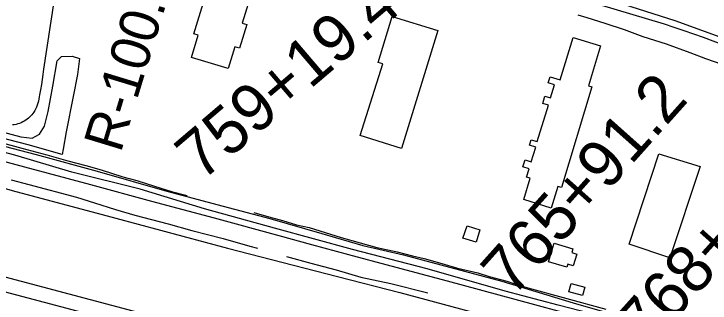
# Model space of a CAD drawing. Extents: x 3651524 to 3689615, y 505651 to 531377.
# Drawn here: x 3663457 to 3664931, y 512320 to 512932 of the extents above; entities that cross this region are included whole.
import ezdxf

# ---------------------------------------------------------------- set-up
doc = ezdxf.new("R2010")
doc.units = 0
for name, color, linetype in [('V-BLDG-OTLN', 7, 'Continuous'), ('V-LEVE-TOET', 7, 'Continuous'), ('V-RAIL-TRAK', 7, 'Continuous'), ('V-RIVR-RANG-IDEN', 7, 'Continuous'), ('V-ROAD-CNTR', 7, 'Continuous'), ('V-SITE-VEGE', 7, 'Continuous'), ('V-SURV-IDEN', 7, 'Continuous'), ('V-TOPO-SHOR', 7, 'Continuous')]:
    doc.layers.add(name, color=color, linetype=linetype)

msp = doc.modelspace()

# ---------------------------------------------------------------- linework, layer by layer
at = {"layer": 'V-BLDG-OTLN'}
for points in [[(3663885.035, 513007.64), (3663962.224, 512984.524), (3663940.769, 512912.879), (3663950.118, 512910.118), (3663935.043, 512859.715), (3663924.733, 512862.76), (3663910.705, 512816.776), (3663833.2, 512840.416), (3663847.593, 512887.606), (3663838.322, 512890.437), (3663860.983, 512964.101), (3663870.285, 512961.273)], [(3664258.416, 512927.217), (3664354.766, 512897.449), (3664277.819, 512647.253), (3664190.496, 512674.674), (3664238.231, 512826.74), (3664228.304, 512829.84)], [(3664641.103, 512882.224), (3664699.443, 512864.556), (3664673.775, 512779.769), (3664680.861, 512777.842), (3664616.458, 512564.481), (3664608.755, 512566.834), (3664594.511, 512521.24), (3664536.622, 512539.319), (3664550.69, 512584.488), (3664542.754, 512586.751), (3664548.353, 512604.356), (3664534.847, 512608.488), (3664539.533, 512623.261), (3664552.734, 512619.255), (3664562.481, 512649.881), (3664548.687, 512654.142), (3664552.408, 512665.849), (3664565.264, 512661.904), (3664588.996, 512739.302), (3664576.917, 512743.011), (3664581.599, 512758.302), (3664593.6, 512754.617), (3664601.937, 512782.337), (3664588.656, 512786.396), (3664592.549, 512799.223), (3664613.762, 512792.661)], [(3664823, 512636.331), (3664910.131, 512609.041), (3664846.348, 512416.015), (3664759.666, 512444.657)], [(3664417.046, 512483.804), (3664444.108, 512475.293), (3664435.724, 512448.636), (3664408.039, 512457.401)], [(3664640.8, 512434.808), (3664638.257, 512427.029), (3664649.088, 512423.486), (3664641.187, 512399.009), (3664629.954, 512402.546), (3664627.834, 512395.818), (3664589.252, 512407.203), (3664600.844, 512446.569)], [(3664637.126, 512361.242), (3664666.314, 512353.67), (3664661.423, 512335.769), (3664632.336, 512343.721)]]:
    msp.add_lwpolyline(points, close=True, dxfattribs=at)
at = {"layer": 'V-LEVE-TOET'}
msp.add_lwpolyline([(3664386.871, 513072.496), (3664533.157, 513026.422), (3664686.155, 512973.7), (3664856.979, 512918.834), (3665006.421, 512864.314), (3665127.78, 512816.344), (3665265.743, 512759.809), (3665352.875, 512716.488), (3665511.962, 512638.232), (3665685.632, 512545.793), (3665843.402, 512463.078), (3665924.19, 512424.269), (3665981.294, 512403.16)], dxfattribs=at)
at = {"layer": 'V-RAIL-TRAK'}
msp.add_lwpolyline([(3663335.137, 512647.687), (3663479.605, 512608.732), (3663619.391, 512570.869), (3663748.253, 512535.625), (3663881.125, 512500.399), (3664018.237, 512462.97), (3664087.127, 512444.145), (3664165.379, 512423.136), (3664255.225, 512399.064), (3664374.722, 512366.894), (3664518.076, 512327.935), (3664658.085, 512290.072), (3664818.38, 512246.738), (3664939.661, 512214.132), (3665071.646, 512178.011), (3665233.95, 512134.02), (3665375.516, 512096.165), (3665508.618, 512059.383), (3665631.629, 512026.861), (3665721.3, 512002.936)], dxfattribs=at)
at = {"layer": 'V-ROAD-CNTR'}
for points in [[(3664834.627, 512910.803), (3664389.456, 513044.493), (3663732.502, 513248.187), (3663284.792, 513384.686)], [(3663558.551, 513161.592), (3663557.963, 513155.311), (3663557.58, 513149.013), (3663557.402, 513142.705), (3663557.425, 513136.397), (3663557.654, 513130.091), (3663558.086, 513123.798), (3663558.721, 513117.521), (3663559.559, 513111.266), (3663560.597, 513105.044), (3663561.187, 513100.348), (3663561.545, 513095.63), (3663561.672, 513090.899), (3663561.568, 513086.168), (3663561.23, 513081.447), (3663560.66, 513076.749), (3663559.862, 513072.086), (3663541.688, 512958.885), (3663520.096, 512815.386)], [(3663520.096, 512815.386), (3663518.785, 512804.447), (3663517.263, 512793.537), (3663515.533, 512782.659), (3663513.593, 512771.816), (3663511.445, 512761.013)], [(3662687.803, 512769.002), (3662856.968, 512724.032), (3663049.631, 512672.144), (3663229.138, 512623.709), (3663453.403, 512558.308), (3663673.319, 512499.738), (3663909.683, 512436.082), (3664142.088, 512376.35), (3664274.501, 512342.148), (3664531.07, 512273.425), (3664745.832, 512213.421), (3664943.198, 512159.44), (3665064.451, 512122.932), (3665250.097, 512066.549), (3665457.34, 512008.388), (3665552.273, 511980.205)], [(3663511.445, 512761.013), (3663511.017, 512756.512), (3663510.331, 512752.043), (3663509.387, 512747.621), (3663508.191, 512743.259), (3663506.745, 512738.977), (3663505.055, 512734.78), (3663503.126, 512730.691), (3663501.444, 512727.582), (3663499.587, 512724.575), (3663497.559, 512721.679), (3663495.37, 512718.902), (3663493.025, 512716.258), (3663490.535, 512713.752), (3663487.903, 512711.39), (3663485.142, 512709.187), (3663482.259, 512707.143), (3663479.265, 512705.267), (3663476.166, 512703.567), (3663472.977, 512702.047), (3663469.381, 512700.65), (3663465.703, 512699.475), (3663461.963, 512698.521), (3663458.17, 512697.796), (3663454.343, 512697.3)], [(3665236.632, 512025.479), (3665227.655, 512027.148), (3664921.399, 512071.698), (3664592.502, 512121.721), (3663946.414, 512239.672), (3663146.005, 512452.151), (3662753.566, 512556.239)], [(3665231.148, 511995.985), (3665222.753, 511997.546), (3664916.985, 512042.024), (3664587.552, 512092.129), (3663939.862, 512210.373), (3663138.311, 512423.155), (3662772.8, 512520.099)]]:
    msp.add_lwpolyline(points, dxfattribs=at)
msp.add_arc((3663807.211, 509792.638), 3283.068, 65.657118, 71.763262, dxfattribs=at)
at = {"layer": 'V-SITE-VEGE'}
for points in [[(3663254.626, 512730.123), (3663472.162, 512672.077), (3663495.599, 512669.132), (3663511.515, 512677.692), (3663522.297, 512694.717), (3663529.961, 512725.644), (3663539.554, 512779.328), (3663548.804, 512833.347), (3663558.268, 512842.218), (3663580.671, 512842.661), (3663595.968, 512838.321), (3663592.056, 512804.013), (3663582.769, 512757.466), (3663568.183, 512682.712), (3663561.228, 512646.016), (3663559.583, 512634.465), (3663487.178, 512655.175), (3663358.023, 512688.174)], [(3665777.713, 512006), (3665679.843, 512027.946), (3665587.4, 512050.595), (3665484.406, 512078.968), (3665365.102, 512110.996), (3665226.086, 512147.684), (3665112.557, 512178.587), (3664990.064, 512210.396), (3664856.346, 512246.5), (3664727.166, 512284.931), (3664609.974, 512315.274), (3664497.469, 512344.958), (3664332.263, 512392.728), (3664174.219, 512433.061), (3664009.361, 512478.795), (3663860.819, 512519.511), (3663724.836, 512560.967), (3663580.053, 512597.29), (3663459.032, 512633.046), (3663243.88, 512690.085)], [(3663335.794, 512678.567), (3663504.377, 512634.547), (3663633.545, 512599.17), (3663780.734, 512556.75), (3663900.374, 512525.399), (3663998.945, 512499.385), (3664109.422, 512467.314), (3664195.77, 512441.581), (3664282.425, 512422.299), (3664490.104, 512366.243), (3664641.724, 512320.447), (3664786.876, 512278.697), (3664922.828, 512243.688), (3665027.161, 512218.717), (3665122.344, 512190.989), (3665186.279, 512166.507), (3665251.182, 512153.234), (3665370.144, 512121.544), (3665633.81, 512057.263), (3665778.694, 512013.813)]]:
    msp.add_lwpolyline(points, dxfattribs=at)
at = {"layer": 'V-TOPO-SHOR'}
for points in [[(3664650.96, 512930.866), (3664670.394, 512924.583), (3664708.425, 512912.565), (3664749.51, 512899.177), (3664789.217, 512884.95), (3664838.074, 512869.379), (3664888.332, 512850.767), (3664921.376, 512838.172), (3664956.36, 512825.861), (3664982.456, 512817.393), (3665004.666, 512809.459), (3665034.096, 512799.339), (3665052.7, 512792.221)], [(3663423.854, 512661.788), (3663474.087, 512648.164), (3663526.817, 512634.277), (3663571.505, 512621.458), (3663609.526, 512611.382), (3663642.001, 512601.832), (3663687.802, 512587.636), (3663717.777, 512579.46), (3663754.973, 512567.717), (3663790.784, 512556.244), (3663824.363, 512547.532)], [(3663451.553, 512580.826), (3663488.61, 512571.36), (3663589.818, 512544.466), (3663628.13, 512532.516), (3663672.674, 512517.797), (3663713.163, 512505.857), (3663784.161, 512487.527), (3663834.302, 512473.458), (3663900.004, 512456.971), (3663956.688, 512440.131), (3663973.189, 512436.166)], [(3663965.618, 512511.606), (3663996.979, 512502.883), (3664026.122, 512494.706), (3664055.267, 512485.973), (3664082.458, 512480.28), (3664149.913, 512458.7), (3664190.158, 512447.245), (3664225.683, 512437.712), (3664268.689, 512428.49), (3664301.158, 512420.326), (3664325.578, 512414.066), (3664363.323, 512403.711), (3664396.353, 512394.163), (3664439.365, 512383.833), (3664463.791, 512376.464), (3664501.256, 512366.661), (3664513.474, 512362.008)], [(3664034.234, 512418.414), (3664085.616, 512404.348), (3664139.489, 512390.604), (3664191.502, 512374.986), (3664255.387, 512361.043), (3664333.481, 512341.753)], [(3664513.474, 512362.008), (3664545.394, 512352.456), (3664710.254, 512306.941)]]:
    msp.add_lwpolyline(points, dxfattribs=at)

# ---------------------------------------------------------------- texts
at = {"layer": 'V-RIVR-RANG-IDEN'}
msp.add_text('R-100.6', height=83, rotation=73.055193, dxfattribs=at).set_placement((3663683.279, 512636.223))
at = {"layer": 'V-SURV-IDEN'}
for s, rotation, p in [('759+19.4', 40.440881, (3663854.688, 512576.343)), ('765+91.2', 48.257534, (3664513.675, 512330.483)), ('768+44.8', 48.170424, (3664800.32, 512220.96)), ('771+42.5', 48.11708, (3664806.748, 512027.854))]:
    msp.add_text(s, height=100, rotation=rotation, dxfattribs=at).set_placement(p)

doc.saveas('drawing.dxf')
